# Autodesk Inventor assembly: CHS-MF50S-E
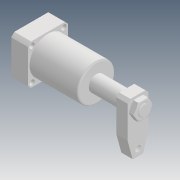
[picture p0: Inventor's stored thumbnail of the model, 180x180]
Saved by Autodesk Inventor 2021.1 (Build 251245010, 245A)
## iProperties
Created: 2019-04
Part Number: CHS-MF50S-E
Description: STEP AP203
Document SubType Name: Assembly
Designer: user
Title: chs-mf50S-e_asm.STEP
Revision Number: ÈÎºÎ
Sending System: SolidWorks 2017
Preprocessor: SwSTEP 2.0
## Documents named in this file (11)
- D:\Vault_2016\Projekty\Clamptek\Hydraulic\CHS\CHS-50\Inventor\CHS-MF50S-E\CHS-MF50S-E.iam
- D:\Vault_2016\Projekty\Clamptek\Hydraulic\CHS\CHS-50\Inventor\CHS-MF50S-E\CHS-MF50EBT.ipt
- D:\Vault_2016\Projekty\Clamptek\Hydraulic\CHS\CHS-50\Inventor\CHS-MF50S-E\CHS-50-ESHSG_1.ipt
- D:\Vault_2016\Projekty\Clamptek\Hydraulic\CHS\CHS-50\Inventor\CHS-MF50S-E\M6_3.ipt
- D:\Vault_2016\Projekty\Clamptek\Hydraulic\CHS\CHS-50\Inventor\CHS-MF50S-E\PRT0002_2.ipt
- D:\Vault_2016\Projekty\Clamptek\Hydraulic\CHS\CHS-50\Inventor\CHS-MF50S-E\M6LM_2.ipt
- D:\Vault_2016\Projekty\Clamptek\Hydraulic\CHS\CHS-50\Inventor\CHS-MF50S-E\PRT0003_2.ipt
- D:\Vault_2016\Projekty\Clamptek\Hydraulic\CHS\CHS-50\Inventor\CHS-MF50S-E\PRT0001_2.ipt
- D:\Vault_2016\Projekty\Clamptek\Hydraulic\CHS\CHS-50\Inventor\CHS-MF50S-E\PRT0006_2.ipt
- D:\Vault_2016\Projekty\Clamptek\Hydraulic\CHS\CHS-50\Inventor\CHS-MF50S-E\CHS-50SYB_5.ipt
- D:\Vault_2016\Projekty\Clamptek\Hydraulic\CHS\CHS-50\Inventor\CHS-MF50S-E\M20LM_5.ipt
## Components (11 placed, 11 different names)
1. CHS-MF50EBT_1
2. CHS-50-ESHSG_1_2
3. M6_3_3
4. M6_3_4
5. PRT0002_2_5
6. M6LM_2_6
7. PRT0003_2_7
8. PRT0001_2_8
9. PRT0006_2_9
10. CHS-50SYB_5_10
11. M20LM_5_11
